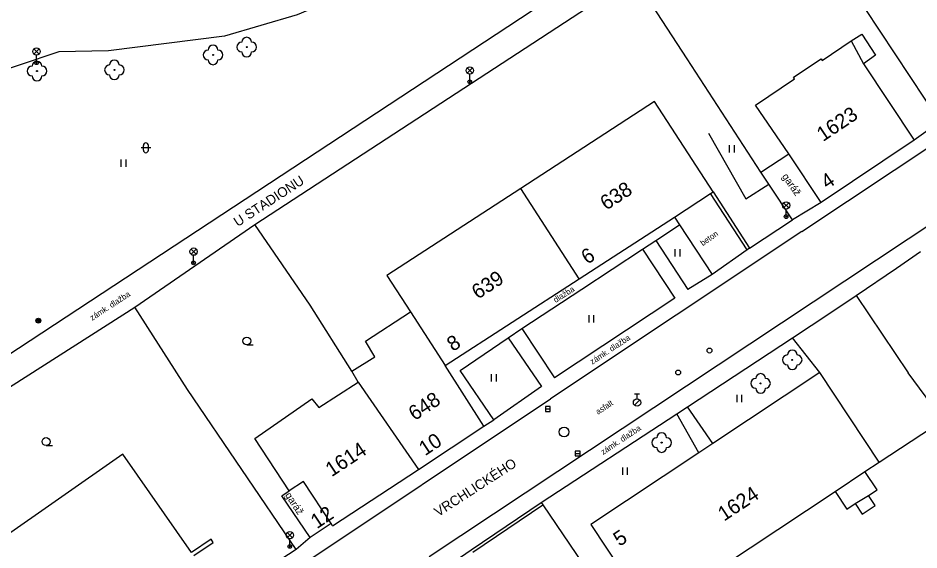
# Model space of a CAD drawing. Extents: x -493753 to -49290, y -1127285 to -112654.
# Drawn here: x -493060.6 to -492968.4, y -1126963.3 to -1126908.9 of the extents above; entities that cross this region are included whole.
import ezdxf

# ---------------------------------------------------------------- set-up
doc = ezdxf.new("R2010")
doc.units = 0
for name, color, linetype in [('Vrstva 10', 7, 'Continuous'), ('Vrstva 11', 7, 'Continuous'), ('Vrstva 22', 7, 'Continuous'), ('Vrstva 25', 7, 'Continuous'), ('Vrstva 27', 7, 'Continuous'), ('Vrstva 28', 7, 'Continuous'), ('Vrstva 33', 7, 'Continuous'), ('Vrstva 36', 7, 'Continuous'), ('Vrstva 40', 7, 'Continuous'), ('Vrstva 41', 7, 'Continuous'), ('Vrstva 43', 7, 'Continuous'), ('Vrstva 44', 7, 'Continuous'), ('Vrstva 45', 7, 'Continuous'), ('Vrstva 5', 7, 'Continuous'), ('Vrstva 7', 7, 'Continuous'), ('Vrstva 8', 7, 'Continuous')]:
    doc.layers.add(name, color=color, linetype=linetype)

msp = doc.modelspace()

# ---------------------------------------------------------------- linework, layer by layer
at = {"layer": 'Vrstva 10'}
for p, q in [((-492980.41, -1126930.75), (-492949.94, -1126910.49)), ((-492962.24, -1126926.69), (-492988.97, -1126944.41)), ((-492995.36, -1126931.68), (-492992.93, -1126930.08)), ((-492992.93, -1126930.08), (-492989.59, -1126935.16)), ((-492980.41, -1126930.75), (-493006.11, -1126947.86)), ((-492995.36, -1126931.68), (-492992.06, -1126936.69)), ((-493002.93, -1126936.65), (-492996.7, -1126932.56)), ((-492996.7, -1126932.56), (-492993.4, -1126937.58)), ((-492989.59, -1126935.16), (-492992.06, -1126936.69)), ((-493009.04, -1126940.67), (-493002.93, -1126936.65)), ((-492993.4, -1126937.58), (-493005.72, -1126945.72)), ((-493009.04, -1126940.67), (-493005.72, -1126945.72)), ((-493015.37, -1126944.97), (-493010.45, -1126941.61)), ((-493010.45, -1126941.61), (-493007.03, -1126946.61)), ((-492988.97, -1126944.41), (-493018.54, -1126964.04)), ((-493011.91, -1126950.01), (-493015.37, -1126944.97)), ((-493007.03, -1126946.61), (-493011.91, -1126950.01)), ((-493055.45, -1126980.77), (-493006.11, -1126947.86))]:
    msp.add_line(p, q, dxfattribs=at)
for points in [[(-493007.99, -1126908.18), (-493015.55, -1126900.87), (-493023.51, -1126904.99), (-493032.02, -1126908.6), (-493039.47, -1126910.76), (-493051.35, -1126912.28), (-493056.41, -1126912.39), (-493080.81, -1126920.54)], [(-492989.95, -1126920.7), (-492986.13, -1126927.41), (-492983.78, -1126925.92)], [(-492985.75, -1126932.47), (-492986, -1126932.63), (-492989.74, -1126926.86)], [(-492989.49, -1126926.7), (-492985.75, -1126932.47)], [(-492978.57, -1126945.18), (-492981.37, -1126941.62)], [(-492989.53, -1126952.44), (-492992.11, -1126948.69)], [(-492990.94, -1126953.38), (-492993.19, -1126949.4)]]:
    msp.add_lwpolyline(points, dxfattribs=at)
at = {"layer": 'Vrstva 11'}
for p, q in [((-492993.45, -1126929.27), (-492992.93, -1126930.08)), ((-492985.75, -1126932.47), (-492981.38, -1126929.56)), ((-492996.7, -1126932.56), (-492995.36, -1126931.68)), ((-492986, -1126932.63), (-492989.59, -1126935.16)), ((-493010.45, -1126941.61), (-493009.04, -1126940.67)), ((-493012.93, -1126950.66), (-493011.91, -1126950.01))]:
    msp.add_line(p, q, dxfattribs=at)
for points in [[(-492965.96, -1126950.06), (-492969.54, -1126945.19)], [(-492972.49, -1126954.34), (-492965.96, -1126950.06)], [(-492972.71, -1126957.18), (-492973.95, -1126955.31)], [(-492973.58, -1126957.75), (-492972.71, -1126957.18)], [(-492977, -1126957.33), (-492975.8, -1126959.14)], [(-492974.95, -1126958.58), (-492973.58, -1126957.75)], [(-492972.91, -1126958.76), (-492973.58, -1126957.75)], [(-492975.8, -1126959.14), (-492974.95, -1126958.58)], [(-492974.95, -1126958.58), (-492974.24, -1126959.65)], [(-492974.24, -1126959.65), (-492972.91, -1126958.76)]]:
    msp.add_lwpolyline(points, dxfattribs=at)
at = {"layer": 'Vrstva 22'}
for centre in [(-493037.2, -1126911.89), (-493040.64, -1126912.69), (-493058.65, -1126914.34), (-493050.73, -1126914.22), (-492981.39, -1126943.88), (-492984.63, -1126946.29), (-492994.75, -1126952.34)]:
    msp.add_circle(centre, 0.05, dxfattribs=at)
for centre, start, end in [((-493037.2, -1126911.39), 360, 180), ((-493040.64, -1126912.19), 360, 180), ((-493037.7, -1126911.89), 90, 270), ((-493036.7, -1126911.89), 270, 90), ((-493041.14, -1126912.69), 90, 270), ((-493040.14, -1126912.69), 270, 90), ((-493037.2, -1126912.39), 180, 0), ((-493059.15, -1126914.34), 90, 270), ((-493058.65, -1126913.84), 360, 180), ((-493058.15, -1126914.34), 270, 90), ((-493051.23, -1126914.22), 90, 270), ((-493050.73, -1126913.72), 360, 180), ((-493050.23, -1126914.22), 270, 90), ((-493040.64, -1126913.19), 180, 0), ((-493058.65, -1126914.84), 180, 0), ((-493050.73, -1126914.72), 180, 0), ((-492981.89, -1126943.88), 90, 270), ((-492981.39, -1126943.38), 0, 180), ((-492980.89, -1126943.88), 270, 90), ((-492981.39, -1126944.38), 180, 0), ((-492984.63, -1126945.79), 0, 180), ((-492985.13, -1126946.29), 90, 270), ((-492984.13, -1126946.29), 270, 90), ((-492984.63, -1126946.79), 180, 0), ((-492994.75, -1126951.84), 0, 180), ((-492995.25, -1126952.34), 90, 270), ((-492994.25, -1126952.34), 270, 90), ((-492994.75, -1126952.84), 180, 0)]:
    msp.add_arc(centre, 0.5, start, end, dxfattribs=at)
at = {"layer": 'Vrstva 25'}
for radius in [0.25, 0.158, 0.05]:
    msp.add_circle((-493058.51, -1126939.87), radius, dxfattribs=at)
at = {"layer": 'Vrstva 27'}
for p, q in [((-493006.64, -1126948.9), (-493006.14, -1126948.9)), ((-493003.6, -1126953.46), (-493003.1, -1126953.46))]:
    msp.add_line(p, q, dxfattribs=at)
for points in [[(-493006.64, -1126949.15), (-493006.14, -1126949.15), (-493006.14, -1126948.65), (-493006.64, -1126948.65)], [(-493003.6, -1126953.71), (-493003.1, -1126953.71), (-493003.1, -1126953.21), (-493003.6, -1126953.21)]]:
    msp.add_lwpolyline(points, close=True, dxfattribs=at)
msp.add_circle((-493004.73, -1126951.25), 0.5, dxfattribs=at)
at = {"layer": 'Vrstva 28'}
for p, q in [((-492997.535, -1126948.515), (-492997.005, -1126947.985)), ((-492997.52, -1126947.35), (-492997.02, -1126947.35)), ((-492997.27, -1126947.875), (-492997.27, -1126947.35))]:
    msp.add_line(p, q, dxfattribs=at)
for centre, radius in [((-492989.86, -1126942.93), 0.25), ((-492993.06, -1126945.17), 0.25), ((-492997.27, -1126948.25), 0.375)]:
    msp.add_circle(centre, radius, dxfattribs=at)
at = {"layer": 'Vrstva 33'}
for p, q in [((-493058.965, -1126912.075), (-493058.435, -1126912.605)), ((-493058.965, -1126912.605), (-493058.435, -1126912.075)), ((-493058.7, -1126913.49), (-493058.7, -1126912.715)), ((-493014.645, -1126914.015), (-493014.115, -1126914.545)), ((-493014.645, -1126914.545), (-493014.115, -1126914.015)), ((-493014.38, -1126915.43), (-493014.38, -1126914.655)), ((-492982.285, -1126927.815), (-492981.755, -1126928.345)), ((-492982.285, -1126928.345), (-492981.755, -1126927.815)), ((-492982.02, -1126929.23), (-492982.02, -1126928.455)), ((-493042.895, -1126932.545), (-493042.365, -1126933.075)), ((-493042.895, -1126933.075), (-493042.365, -1126932.545)), ((-493042.63, -1126933.96), (-493042.63, -1126933.185)), ((-493033.055, -1126961.545), (-493032.525, -1126962.075)), ((-493033.055, -1126962.075), (-493032.525, -1126961.545)), ((-493032.79, -1126962.96), (-493032.79, -1126962.185))]:
    msp.add_line(p, q, dxfattribs=at)
for centre, radius in [((-493058.7, -1126912.34), 0.375), ((-493058.7, -1126913.49), 0.19), ((-493058.7, -1126913.49), 0.05), ((-493014.38, -1126914.28), 0.375), ((-493014.38, -1126915.43), 0.19), ((-493014.38, -1126915.43), 0.05), ((-492982.02, -1126928.08), 0.375), ((-492982.02, -1126929.23), 0.19), ((-492982.02, -1126929.23), 0.05), ((-493042.63, -1126932.81), 0.375), ((-493042.63, -1126933.96), 0.19), ((-493042.63, -1126933.96), 0.05), ((-493032.79, -1126961.81), 0.375), ((-493032.79, -1126962.96), 0.19), ((-493032.79, -1126962.96), 0.05)]:
    msp.add_circle(centre, radius, dxfattribs=at)
at = {"layer": 'Vrstva 36'}
for p, q in [((-493047.01, -1126922.19), (-493048.01, -1126922.19)), ((-493047.76, -1126922.44), (-493047.76, -1126921.94)), ((-493047.26, -1126922.44), (-493047.26, -1126921.94)), ((-492987.81, -1126922.68), (-492987.81, -1126921.93)), ((-492987.31, -1126922.68), (-492987.31, -1126921.93)), ((-493050.03, -1126924.15), (-493050.03, -1126923.4)), ((-493049.53, -1126924.15), (-493049.53, -1126923.4)), ((-492993.37, -1126933.32), (-492993.37, -1126932.57)), ((-492992.87, -1126933.32), (-492992.87, -1126932.57)), ((-493002.18, -1126940.07), (-493002.18, -1126939.32)), ((-493001.68, -1126940.07), (-493001.68, -1126939.32)), ((-493037.182, -1126942.35), (-493036.532, -1126942.347)), ((-493012.15, -1126946.1), (-493012.15, -1126945.35)), ((-493011.65, -1126946.1), (-493011.65, -1126945.35)), ((-492987.04, -1126948.19), (-492987.04, -1126947.44)), ((-492986.54, -1126948.19), (-492986.54, -1126947.44)), ((-493057.722, -1126952.64), (-493057.072, -1126952.637)), ((-492998.73, -1126955.64), (-492998.73, -1126954.89)), ((-492998.23, -1126955.64), (-492998.23, -1126954.89))]:
    msp.add_line(p, q, dxfattribs=at)
for centre in [(-493037.182, -1126941.947), (-493057.722, -1126952.237)]:
    msp.add_circle(centre, 0.403, dxfattribs=at)
for centre, start, end in [((-493047.51, -1126921.94), 0, 180), ((-493047.51, -1126922.44), 180, 0)]:
    msp.add_arc(centre, 0.25, start, end, dxfattribs=at)
at = {"layer": 'Vrstva 5'}
for p, q in [((-492975.38, -1126911.26), (-492974.26, -1126910.55)), ((-492974.26, -1126910.55), (-492972.87, -1126912.73)), ((-492978.33, -1126913.27), (-492975.38, -1126911.26)), ((-492981.28, -1126914.98), (-492978.45, -1126913.08)), ((-492978.45, -1126913.08), (-492978.33, -1126913.27)), ((-492972.87, -1126912.73), (-492974.09, -1126913.59)), ((-492974.09, -1126913.59), (-492968.93, -1126921.4)), ((-492985.15, -1126917.82), (-492981.16, -1126915.15)), ((-492981.16, -1126915.15), (-492981.28, -1126914.98)), ((-492981.75, -1126922.8), (-492985.15, -1126917.82)), ((-492968.93, -1126921.4), (-492978.45, -1126927.8)), ((-492978.45, -1126927.8), (-492981.75, -1126922.8)), ((-492972.49, -1126954.34), (-492978.57, -1126945.18)), ((-493049.87, -1126953.52), (-493064.22, -1126963.55)), ((-493002.01, -1126960.71), (-492995.93, -1126969.88))]:
    msp.add_line(p, q, dxfattribs=at)
for points in [[(-492975.38, -1126911.26), (-492974.09, -1126913.59)], [(-492989.49, -1126926.7), (-492995.48, -1126917.47), (-493009.17, -1126926.35)], [(-492984.6, -1126924.68), (-492981.75, -1126922.8)], [(-492981.38, -1126929.56), (-492983.78, -1126925.92), (-492984.6, -1126924.68)], [(-493009.17, -1126926.35), (-493022.86, -1126935.24), (-493020.44, -1126938.98)], [(-493003.18, -1126935.58), (-493009.17, -1126926.35)], [(-493003.18, -1126935.58), (-492993.45, -1126929.27), (-492989.74, -1126926.86)], [(-492989.74, -1126926.86), (-492989.49, -1126926.7)], [(-492978.45, -1126927.8), (-492981.38, -1126929.56)], [(-493016.88, -1126944.47), (-493003.18, -1126935.58)], [(-493025.8, -1126946.17), (-493026.46, -1126945.04), (-493024.08, -1126943.57), (-493025.03, -1126941.96), (-493020.44, -1126938.98)], [(-493020.44, -1126938.98), (-493016.88, -1126944.47)], [(-493019.64, -1126955.09), (-493012.93, -1126950.66), (-493016.88, -1126944.47)], [(-492978.57, -1126945.18), (-492989.53, -1126952.44), (-492990.94, -1126953.38), (-493002.01, -1126960.71)], [(-493032.84, -1126957.27), (-493036.35, -1126951.93), (-493030.52, -1126947.87), (-493029.81, -1126948.75), (-493025.8, -1126946.17)], [(-493025.8, -1126946.17), (-493019.64, -1126955.09)], [(-493042.85, -1126963.57), (-493049.87, -1126953.52)], [(-492973.95, -1126955.31), (-492972.49, -1126954.34)], [(-493028.41, -1126960.87), (-493019.64, -1126955.09)], [(-492977, -1126957.33), (-492973.95, -1126955.31)], [(-493028.56, -1126960.63), (-493031.4, -1126956.32), (-493032.84, -1126957.27)], [(-493033.61, -1126957.77), (-493032.84, -1126957.27)], [(-493028.56, -1126960.63), (-493030.72, -1126962.06), (-493033.61, -1126957.77)], [(-492991.57, -1126966.99), (-492977, -1126957.33)], [(-493028.41, -1126960.87), (-493028.56, -1126960.63)], [(-493042.62, -1126963.89), (-493040.62, -1126962.56), (-493040.85, -1126962.23), (-493042.85, -1126963.57)]]:
    msp.add_lwpolyline(points, dxfattribs=at)
at = {"layer": 'Vrstva 7'}
for p, q in [((-493036.35, -1126930.05), (-492997.6, -1126904.72)), ((-492992.13, -1126913.09), (-492997.6, -1126904.72)), ((-493048.63, -1126938.48), (-493036.35, -1126930.05)), ((-493030.69, -1126938.29), (-493036.35, -1126930.05)), ((-492970.72, -1126934.49), (-492968.26, -1126932.79)), ((-492974.85, -1126937.28), (-492970.72, -1126934.49)), ((-492977.54, -1126939.1), (-492974.85, -1126937.28)), ((-493067.75, -1126950.67), (-493048.63, -1126938.48)), ((-493043.25, -1126946.91), (-493048.63, -1126938.48)), ((-493026.46, -1126945.04), (-493030.69, -1126938.29)), ((-493007.08, -1126958.47), (-492993.19, -1126949.4)), ((-493014.22, -1126963.31), (-493007.08, -1126958.47)), ((-493014.05, -1126963.56), (-493006.91, -1126958.72)), ((-493015.96, -1126964.49), (-493014.22, -1126963.31))]:
    msp.add_line(p, q, dxfattribs=at)
for points in [[(-492984.63, -1126892.83), (-493007.99, -1126908.18), (-493072.81, -1126950.77)], [(-492955.23, -1126902.71), (-492950.78, -1126909.31), (-492966.28, -1126919.52), (-492968.93, -1126921.4)], [(-492977.05, -1126903.26), (-492966.28, -1126919.52)], [(-492984.6, -1126924.68), (-492992.13, -1126913.09)], [(-492974.85, -1126937.28), (-492969.54, -1126945.19)], [(-492993.19, -1126949.4), (-492992.11, -1126948.69), (-492981.37, -1126941.62), (-492977.54, -1126939.1)], [(-493032.15, -1126963.28), (-493043.25, -1126946.91)], [(-493007.08, -1126958.47), (-493006.91, -1126958.72), (-493001.45, -1126966.74)]]:
    msp.add_lwpolyline(points, dxfattribs=at)
at = {"layer": 'Vrstva 8'}
msp.add_lwpolyline([(-493030.72, -1126962.06), (-493032.15, -1126963.28), (-493036.65, -1126966.22)], dxfattribs=at)

# ---------------------------------------------------------------- texts
at = {"layer": 'Vrstva 40'}
for s, rotation, p in [('beton', 35.11948, (-492990.539, -1126932.262)), ('zámk. dlažba', 33.30752, (-493052.994, -1126939.897)), ('dlažba', 32.47109, (-493005.593, -1126938.068)), ('zámk. dlažba', 33.65404, (-493001.835, -1126944.381)), ('asfalt', 33.57814, (-493001.255, -1126949.507)), ('zámk. dlažba', 33.57814, (-493000.737, -1126953.618))]:
    msp.add_text(s, height=0.6, rotation=rotation, dxfattribs=at).set_placement(p)
at = {"layer": 'Vrstva 41'}
for rotation, p in [(305.06578, (-492982.475, -1126925.127)), (303.27098, (-493033.306, -1126957.721))]:
    msp.add_text('garáž', height=0.75, rotation=rotation, dxfattribs=at).set_placement(p)
at = {"layer": 'Vrstva 43'}
for s, rotation, p in [('1623', 33.89377, (-492978.246, -1126921.606)), ('638', 32.9784, (-493000.421, -1126928.629)), ('639', 32.97649, (-493013.562, -1126937.73)), ('648', 33.43314, (-493020.018, -1126950.149)), ('1614', 33.37548, (-493028.513, -1126955.893)), ('1624', 33.54596, (-492988.368, -1126960.436))]:
    msp.add_text(s, height=1.5, rotation=rotation, dxfattribs=at).set_placement(p)
at = {"layer": 'Vrstva 44'}
for s, rotation, p in [('4', 33.89377, (-492977.818, -1126926.473)), ('6', 32.9784, (-493002.363, -1126934.163)), ('8', 32.97649, (-493016.103, -1126943.072)), ('10', 33.43314, (-493018.955, -1126953.743)), ('12', 33.48674, (-493030.018, -1126961.206)), ('5', 33.54596, (-492999.064, -1126963.012))]:
    msp.add_text(s, height=1.5, rotation=rotation, dxfattribs=at).set_placement(p)
at = {"layer": 'Vrstva 45'}
for s, rotation, p in [('U STADIONU', 33.15872, (-493038.117, -1126930.304)), ('VRCHLICKÉHO', 32.87355, (-493017.607, -1126959.962))]:
    msp.add_text(s, height=1, rotation=rotation, dxfattribs=at).set_placement(p)

doc.saveas('drawing.dxf')
